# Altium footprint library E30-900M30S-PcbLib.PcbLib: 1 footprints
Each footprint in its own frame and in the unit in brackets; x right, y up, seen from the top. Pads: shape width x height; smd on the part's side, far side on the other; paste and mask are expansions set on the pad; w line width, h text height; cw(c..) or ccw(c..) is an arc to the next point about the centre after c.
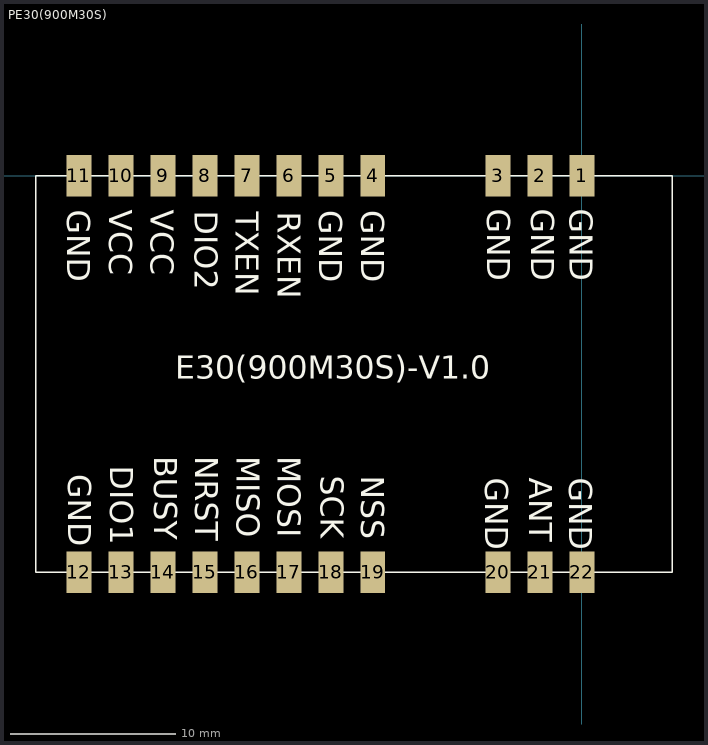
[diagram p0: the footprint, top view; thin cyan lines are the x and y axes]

## PE30(900M30S) [mm] "38.5mm*24mm*3.8mm-S"
pads (22):
  rect 1.5x2.5 smd: 1(0,0) 2(-2.54,0) 3(-5.08,0) 4(-12.65,0) 5(-15.19,0) 6(-17.73,0) 7(-20.27,0) 8(-22.81,0) 9(-25.35,0) 10(-27.89,0) 11(-30.43,0) 12(-30.43,-24) 13(-27.89,-24) 14(-25.35,-24) 15(-22.81,-24) 16(-20.27,-24) 17(-17.73,-24) 18(-15.19,-24) 19(-12.65,-24) 20(-5.08,-24) 21(-2.54,-24) 22(0,-24)
Top Overlay:
  lines w0.1: -33.04,-24 -33.04,0 5.46,0 5.46,-24 -33.04,-24
  text "NSS" at -13.351,-18.17 h1.4
  text "SCK" at -15.816,-18.17 h1.4
  text "MOSI" at -18.416,-16.979 h1.4
  text "MISO" at -20.881,-16.979 h1.4
  text "NRST" at -23.406,-16.979 h1.4
  text "BUSY" at -25.871,-16.979 h1.4
  text "DIO1" at -28.532,-17.552 h1.4
  text "GND" at -31.079,-18.064 h1.4
  text "GND" at -5.844,-18.291 h1.4
  text "ANT" at -3.202,-18.291 h1.4
  text "GND" at -0.775,-18.291 h1.4
  text "GND" at -0.748,-1.991 h1.4
  text "GND" at -3.07,-1.991 h1.4
  text "GND" at -5.743,-1.991 h1.4
  text "GND" at -31.143,-2.051 h1.4
  text "VCC" at -28.61,-2.051 h1.4
  text "VCC" at -26.076,-2.051 h1.4
  text "DIO2" at -23.438,-2.117 h1.4
  text "TXEN" at -20.935,-2.169 h1.4
  text "RXEN" at -18.402,-2.169 h1.4
  text "GND" at -15.899,-2.096 h1.4
  text "GND" at -13.366,-2.096 h1.4
  text "E30(900M30S)-V1.0" at -24.599,-12.278 h1.4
